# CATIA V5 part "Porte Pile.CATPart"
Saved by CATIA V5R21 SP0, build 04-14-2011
Part number: Porte piles
Bounding box of the stored display mesh (mm): x -7 to 20, y 0 to 105, z 0 to 69
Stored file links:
  C:\Users\2027.DESARCY-LEMIE30\Desktop\V16(05.04.2023)\Porte Pile.CATPart
  D:\carte arduino.CATPart
  C:\Users\2027.DESARCY-LEMIE30\Desktop\V15(20.03.2023)\V15(20.03.2023)\Fixation carte arduino v3.CATPart
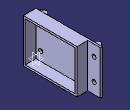
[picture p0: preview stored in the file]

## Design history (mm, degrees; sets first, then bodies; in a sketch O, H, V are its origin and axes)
Body1 (main body)
  Sketch1 on yz-plane, origin (0, 0, 0), H (0, 1, 0), V (0, 0, 1)
    line L1 (0, 0) -> (105, 0)
    line L2 (105, 0) -> (105, 69)
    line L3 (105, 69) -> (0, 69)
    line L4 (0, 69) -> (0, 0)
    length L3 = 105
    length L2 = 69
    horizontal: L1 H, L3 H
    vertical: L2 V, L4 V
  Pad1: profile Sketch1, direction (1, 0, 0), length 3
  Sketch2 on end face of Pad1, origin (3, 0, 0), H (0, 1, 0), V (0, 0, 1)
    line L1 (0, 69) -> (85, 69)
    line L2 (85, 69) -> (85, 0)
    line L3 (85, 0) -> (0, 0)
    line L4 (0, 0) -> (0, 69)
    point P4 (0, 0)
    reference projected line E1 (110, 69) -> (0, 69) from edge [face of Pad1 from Sketch1.L3 | end face of Pad1]
    reference projected line E2 (0, 0) -> (105, 0) from edge [face of Pad1 from Sketch1.L1 | end face of Pad1]
    line L5 (3, 66) -> (82, 66)
    line L6 (82, 66) -> (82, 3)
    line L7 (82, 3) -> (3, 3)
    line L8 (3, 3) -> (3, 66)
    distance L5 L1 = 3
    distance L7 L3 = 3
    distance L6 L2 = 3
    distance L8 L4 = 3
    distance L8 L6 = 79
    horizontal: L1 H, L3 H, L5 H, L7 H
    vertical: L2 V, L4 V, L6 V, L8 V
    coincidence: L1 E1, L3 E2, O P4
  Pad2: profile Sketch2, direction (1, 0, 0), length 17
  Sketch3 on face of Pad2, origin (0, 0, 0), H (1, 0, 0), V (0, -1, 0)
    construction line L1 (-26.9072, -52.5) -> (75.9513, -52.5)
    reference projected line E1 (0, -105) -> (3, -105) from edge [face of Pad1 from Sketch1.L2 | face of Pad1 from Sketch1.L1]
    axis line L2 (-22.3256, -9.9) -> (35.4035, -9.9)
    point P5 (0, -6.9)
    line L3 (0, -6.9) -> (-2.1, -6.9)
    point P6 (-2.1, -6.9)
    line L4 (-2.1, -6.9) -> (-2.1, -3.1)
    point P7 (-2.1, -3.1)
    line L5 (-2.1, -3.1) -> (-7, -8)
    point P8 (-7, -8)
    line L6 (-7, -8) -> (-7, -9.9)
    point P9 (-7, -9.9)
    point P10 (0, -9.9)
    line L7 (0, -9.9) -> (0, -6.9)
    reference projected line E2 (0, 0) -> (0, -105) from edge [start face of Pad1 | face of Pad1 from Sketch1.L1]
    point P11 (0, -12.9)
    point P12 (-2.1, -12.9)
    point P13 (-2.1, -16.7)
    point P14 (-7, -11.8)
    point P15 (-7, -9.9)
    point P16 (0, -9.9)
    line L8 (0, -12.9) -> (-2.1, -12.9)
    line L9 (-2.1, -12.9) -> (-2.1, -16.7)
    line L10 (-2.1, -16.7) -> (-7, -11.8)
    line L11 (-7, -11.8) -> (-7, -9.9)
    line L12 (0, -9.9) -> (0, -12.9)
    point P17 (0, -98.1)
    point P18 (-2.1, -98.1)
    point P19 (-2.1, -101.9)
    point P20 (-7, -97)
    point P21 (-7, -95.1)
    point P22 (0, -95.1)
    point P23 (0, -92.1)
    point P24 (-2.1, -92.1)
    point P25 (-2.1, -88.3)
    point P26 (-7, -93.2)
    point P27 (-7, -95.1)
    point P28 (0, -95.1)
    line L13 (0, -98.1) -> (-2.1, -98.1)
    line L14 (-2.1, -98.1) -> (-2.1, -101.9)
    line L15 (-2.1, -101.9) -> (-7, -97)
    line L16 (-7, -97) -> (-7, -95.1)
    line L17 (0, -95.1) -> (0, -98.1)
    line L18 (0, -92.1) -> (-2.1, -92.1)
    line L19 (-2.1, -92.1) -> (-2.1, -88.3)
    line L20 (-2.1, -88.3) -> (-7, -93.2)
    line L21 (-7, -93.2) -> (-7, -95.1)
    line L22 (0, -95.1) -> (0, -92.1)
    reference projected line E3 (0, 0) -> (3, 0) from edge [face of Pad2 | face of Pad2]
    distance E1 L1 = 52.5
    length L7 = 3
    length L4 = 3.8
    angle L5 L4 = 45
    length L6 = 1.9
    distance L6 L7 = 7
    distance L3 E3 = 6.9
    horizontal: L1 H, L2 H, L3 H
    vertical: L4 V, L6 V, L7 V
    coincidence: P9 L2, P10 L2, L7 E2, P9 P15, P10 P16, P21 P27, P22 P28
    symmetry: P5 P11 L2, P6 P12 L2, P7 P13 L2, P8 P14 L2, P9 P15 L2, P10 P16 L2, L3 L8 L2, L4 L9 L2, L5 L10 L2, L6 L11 L2, L7 L12 L2, P5 P17 L1, P6 P18 L1, P7 P19 L1, P8 P20 L1, P9 P21 L1, P10 P22 L1, P11 P23 L1, P12 P24 L1, P13 P25 L1, P14 P26 L1, P15 P27 L1, P16 P28 L1, L3 L13 L1, L4 L14 L1, L5 L15 L1, L6 L16 L1, L7 L17 L1, L8 L18 L1, L9 L19 L1, L10 L20 L1, L11 L21 L1, L12 L22 L1
  Pad3: profile Sketch3, direction (0, 0, 1), length 67
  Sketch4 on end face of Pad1, origin (3, 16.9157, 27.9903), H (0, 1, 0), V (0, 0, 1)
    point P1 (78.1843, 23.7597)
    construction line L1 (-16.9157, 6.5097) -> (88.0843, 6.5097)
    point P2 (-16.9157, 6.5097)
    point P3 (88.0843, 6.5097)
    reference projected line E1 (88.0843, -27.9903) -> (88.0843, 40.0097) from edge [face of Pad1 from Sketch1.L2 | end face of Pad1]
    reference projected line E2 (-16.9157, 41.0097) -> (-16.9157, -27.9903) from edge [face of Pad2 | end face of Pad2]
    construction line L2 (35.5843, 6.5097) -> (35.5843, 41.0097)
    point P4 (35.5843, 6.5097)
    point P5 (35.5843, 41.0097)
    reference projected line E3 (68.0843, 41.0097) -> (-16.9157, 41.0097) from edge [face of Pad3 | end face of Pad2]
    reference projected line E4 (93.0843, 41.0097) -> (-16.9157, 41.0097) from edge [face of Pad3 | end face of Pad1]
    reference projected line E5 (-16.9157, -27.9903) -> (88.0843, -27.9903) from edge [face of Pad3 | end face of Pad1]
    reference projected line E6 (93.0843, 41.0097) -> (-16.9157, 41.0097) from edge [face of Pad3 | end face of Pad1]
    construction line L3 (35.5843, 23.7597) -> (88.0843, 23.7597)
    point P6 (35.5843, 23.7597)
    point P7 (88.0843, 23.7597)
    reference projected line E7 (88.0843, -27.9903) -> (88.0843, 40.0097) from edge [face of Pad1 from Sketch1.L2 | end face of Pad1]
    axis line L4 (78.1843, 41.0097) -> (78.1843, -27.9903)
    point P8 (78.1843, 41.0097)
    point P9 (78.1843, -27.9903)
    reference projected line E8 (68.0843, 41.0097) -> (-16.9157, 41.0097) from edge [face of Pad3 | end face of Pad2]
    reference projected line E9 (-16.9157, -27.9903) -> (68.0843, -27.9903) from edge [face of Pad3 | end face of Pad2]
    reference projected line E10 (88.0843, -27.9903) -> (88.0843, 40.0097) from edge [face of Pad1 from Sketch1.L2 | end face of Pad1]
    distance E4 E5 = 69 (reference)
    distance L1 E6 = 34.5
    distance L4 E10 = 9.9
    horizontal: L1 H, L3 H
    coincidence: P3 E1, P2 E2, P5 E3, P7 E7, E8 P8, P9 E9, P1 L4, P1 L3
    vertical: L2 V, L4 V
    midpoint: P4 L1, P6 L2
  Hole1: placed by Sketch4, at (3, 95.1, 51.75) direction (-1, 0, 0), diameter 3.8, depth 12, counterbore diameter 6.8, counterbore depth 4
  RectPattern1: of Hole1, direction 1 instances 2, spacing 84.7, along end face of Pad1 reversed, direction 2 instances 2, spacing -34.5, along end face of Pad1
